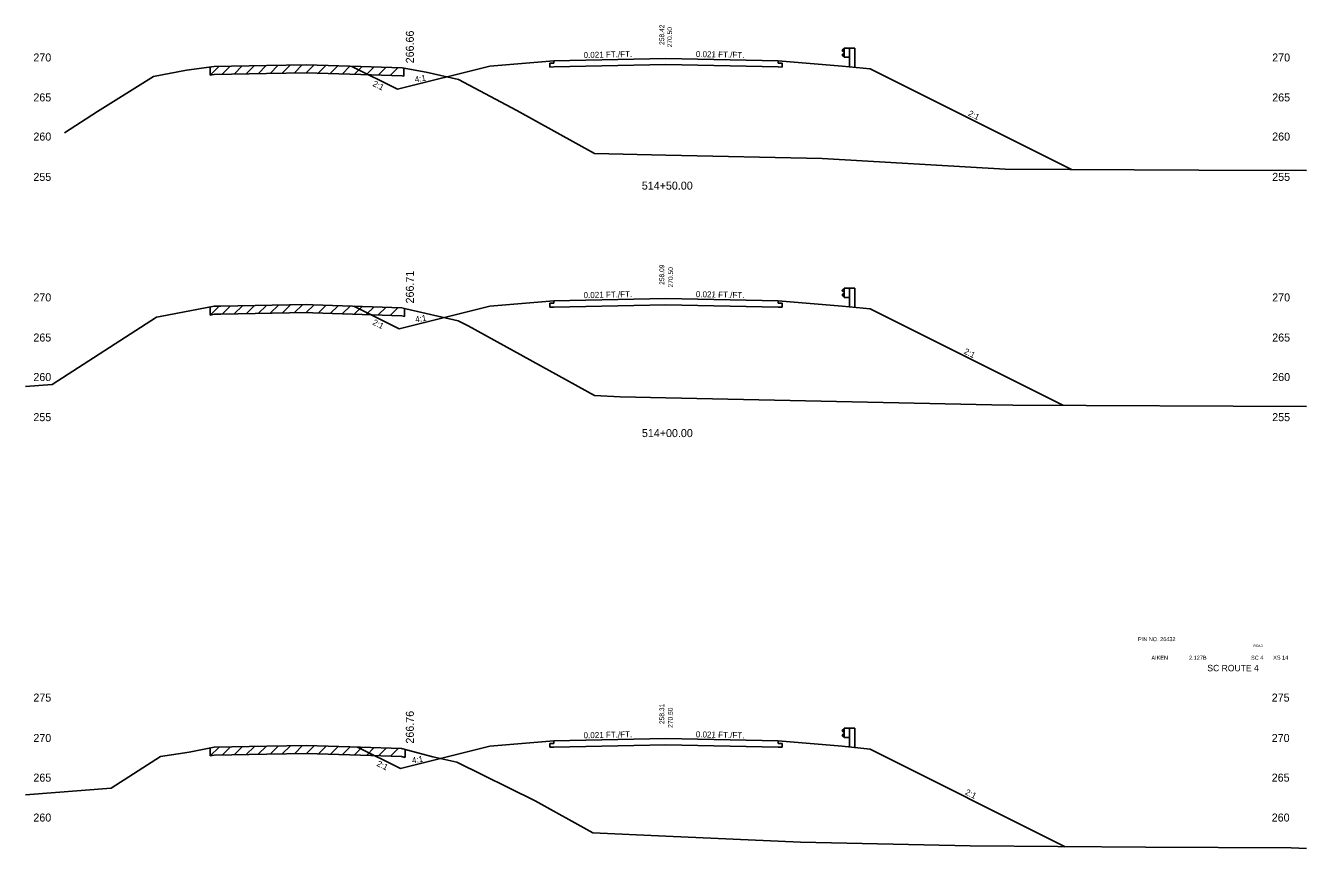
# Model space of a CAD drawing. Extents: x 883 to 1160, y 1002 to 4323.
# Drawn here: x 1000 to 1160, y 2571.8 to 2674.6 of the extents above; entities that cross this region are included whole.
import ezdxf

# ---------------------------------------------------------------- set-up
doc = ezdxf.new("R2010")
doc.units = 0
for name, color, linetype in [('Level 1', 7, 'Continuous'), ('Level 10', 7, 'Continuous'), ('Level 11', 7, 'Continuous'), ('Level 12', 7, 'Continuous'), ('Level 24', 7, 'Continuous'), ('Level 3', 7, 'Continuous'), ('Level 32', 7, 'Continuous'), ('Level 33', 7, 'Continuous'), ('Level 59', 7, 'Continuous'), ('Level 6', 7, 'Continuous'), ('Level 60', 7, 'Continuous'), ('Level 61', 7, 'Continuous'), ('Level 7', 7, 'Continuous')]:
    doc.layers.add(name, color=color, linetype=linetype)

msp = doc.modelspace()

# ---------------------------------------------------------------- linework, layer by layer
at = {"layer": 'Level 11'}
for p, q in [((1066, 2669.91), (1065.5, 2669.9)), ((1065.5, 2669.9), (1065.5, 2669.42)), ((1065.5, 2669.42), (1066, 2669.43)), ((1066, 2670.21), (1066, 2669.91)), ((1094, 2669.91), (1094, 2670.21)), ((1094.5, 2669.9), (1094, 2669.91)), ((1094, 2669.43), (1094.5, 2669.42)), ((1094.5, 2669.42), (1094.5, 2669.9)), ((1066, 2640.21), (1066, 2639.91)), ((1094, 2639.91), (1094, 2640.21)), ((1066, 2639.91), (1065.5, 2639.9)), ((1065.5, 2639.9), (1065.5, 2639.42)), ((1065.5, 2639.42), (1066, 2639.43)), ((1094.5, 2639.9), (1094, 2639.91)), ((1094, 2639.43), (1094.5, 2639.42)), ((1094.5, 2639.42), (1094.5, 2639.9)), ((1066, 2584.91), (1065.5, 2584.9)), ((1065.5, 2584.9), (1065.5, 2584.42)), ((1065.5, 2584.42), (1066, 2584.43)), ((1066, 2585.21), (1066, 2584.91)), ((1094, 2584.91), (1094, 2585.21)), ((1094.5, 2584.9), (1094, 2584.91)), ((1094, 2584.43), (1094.5, 2584.42)), ((1094.5, 2584.42), (1094.5, 2584.9))]:
    msp.add_line(p, q, dxfattribs=at)
at = {"layer": 'Level 12'}
for p, q in [((1080, 2669.72), (1066, 2669.43)), ((1094, 2669.43), (1080, 2669.72)), ((1080, 2639.72), (1066, 2639.43)), ((1094, 2639.43), (1080, 2639.72)), ((1080, 2584.72), (1066, 2584.43)), ((1094, 2584.43), (1080, 2584.72))]:
    msp.add_line(p, q, dxfattribs=at)
at = {"layer": 'Level 24'}
for p, q in [((1102.27, 2671.72), (1102, 2671.52)), ((1102, 2671.52), (1102, 2671.47)), ((1102, 2671.47), (1102.27, 2671.27)), ((1102, 2670.95), (1102.27, 2671.15)), ((1102, 2670.9), (1102, 2670.95)), ((1102.27, 2670.7), (1102, 2670.9)), ((1102.27, 2670.63), (1102.27, 2671.79)), ((1102.27, 2671.79), (1102.94, 2671.79)), ((1102.27, 2670.63), (1102.94, 2670.63)), ((1102.94, 2671.79), (1102.94, 2669.45)), ((1102.94, 2671.79), (1103.6, 2671.79)), ((1103.6, 2671.79), (1103.6, 2669.38)), ((1102.27, 2641.72), (1102, 2641.52)), ((1102.27, 2640.63), (1102.27, 2641.79)), ((1102.27, 2641.79), (1102.94, 2641.79)), ((1102.94, 2641.79), (1102.94, 2639.45)), ((1102.94, 2641.79), (1103.6, 2641.79)), ((1103.6, 2641.79), (1103.6, 2639.38)), ((1102, 2641.52), (1102, 2641.47)), ((1102, 2641.47), (1102.27, 2641.27)), ((1102, 2640.95), (1102.27, 2641.15)), ((1102, 2640.9), (1102, 2640.95)), ((1102.27, 2640.7), (1102, 2640.9)), ((1102.27, 2640.63), (1102.94, 2640.63)), ((1102.27, 2586.72), (1102, 2586.52)), ((1102, 2586.52), (1102, 2586.47)), ((1102, 2586.47), (1102.27, 2586.27)), ((1102, 2585.95), (1102.27, 2586.15)), ((1102, 2585.9), (1102, 2585.95)), ((1102.27, 2585.7), (1102, 2585.9)), ((1102.27, 2585.63), (1102.27, 2586.79)), ((1102.27, 2586.79), (1102.94, 2586.79)), ((1102.27, 2585.63), (1102.94, 2585.63)), ((1102.94, 2586.79), (1102.94, 2584.45)), ((1102.94, 2586.79), (1103.6, 2586.79)), ((1103.6, 2586.79), (1103.6, 2584.38))]:
    msp.add_line(p, q, dxfattribs=at)
at = {"layer": 'Level 59'}
for p, q in [((1066, 2670.21), (1080, 2670.5)), ((1080, 2670.5), (1094, 2670.21)), ((1066, 2640.21), (1080, 2640.5)), ((1080, 2640.5), (1094, 2640.21)), ((1066, 2585.21), (1080, 2585.5)), ((1080, 2585.5), (1094, 2585.21))]:
    msp.add_line(p, q, dxfattribs=at)
at = {"layer": 'Level 6'}
for p, q in [((1058, 2669.54), (1066, 2670.21)), ((1094, 2670.21), (1102, 2669.54)), ((1102, 2669.54), (1105.5, 2669.19)), ((1058, 2639.54), (1066, 2640.21)), ((1094, 2640.21), (1102, 2639.54)), ((1102, 2639.54), (1105.5, 2639.19)), ((1058, 2584.54), (1066, 2585.21)), ((1094, 2585.21), (1102, 2584.54)), ((1102, 2584.54), (1105.5, 2584.19))]:
    msp.add_line(p, q, dxfattribs=at)
at = {"layer": 'Level 60'}
for p, q in [((1015.97, 2668.23), (1020.09, 2669.02)), ((1020.09, 2669.02), (1023.54, 2669.49)), ((1023.54, 2669.49), (1030.09, 2669.6)), ((1030.09, 2669.6), (1035.05, 2669.69)), ((1035.05, 2669.69), (1041.88, 2669.47)), ((1041.88, 2669.47), (1047.05, 2669.31)), ((1047.05, 2669.31), (1050.04, 2668.79)), ((1008.99, 2663.87), (1015.97, 2668.23)), ((1050.04, 2668.79), (1054.08, 2667.85)), ((1054.08, 2667.85), (1061.38, 2663.98)), ((1004.85, 2661.21), (1008.99, 2663.87)), ((1061.38, 2663.98), (1071.07, 2658.62)), ((1071.07, 2658.62), (1080, 2658.42)), ((1080, 2658.42), (1099.5, 2658)), ((1099.5, 2658), (1122.38, 2656.65)), ((1122.38, 2656.65), (1146.55, 2656.54)), ((1146.55, 2656.54), (1160, 2656.5)), ((1016.8, 2638.23), (1023.55, 2639.53)), ((1023.55, 2639.53), (1024.37, 2639.54)), ((1024.37, 2639.54), (1035.07, 2639.73)), ((1035.07, 2639.73), (1035.89, 2639.7)), ((1035.89, 2639.7), (1047.01, 2639.34)), ((1047.01, 2639.34), (1047.5, 2639.21)), ((1047.5, 2639.21), (1054.05, 2637.69)), ((1003.31, 2629.77), (1016.36, 2638.16)), ((1016.36, 2638.16), (1016.8, 2638.23)), ((1054.05, 2637.69), (1055.28, 2637.08)), ((1055.28, 2637.08), (1071.05, 2628.36)), ((1000, 2629.52), (1003.31, 2629.77)), ((1071.05, 2628.36), (1074.27, 2628.22)), ((1074.27, 2628.22), (1080, 2628.09)), ((1080, 2628.09), (1120.7, 2627.2)), ((1120.7, 2627.2), (1123.34, 2627.18)), ((1123.34, 2627.18), (1160, 2627.01)), ((1020.44, 2583.83), (1023.56, 2584.43)), ((1023.56, 2584.43), (1030.15, 2584.56)), ((1030.15, 2584.56), (1035.09, 2584.65)), ((1035.09, 2584.65), (1041.83, 2584.44)), ((1041.83, 2584.44), (1046.96, 2584.27)), ((1046.96, 2584.27), (1050.87, 2583.24)), ((1010.7, 2579.31), (1016.84, 2583.25)), ((1016.84, 2583.25), (1020.44, 2583.83)), ((1050.87, 2583.24), (1053.88, 2582.54)), ((1053.88, 2582.54), (1063.64, 2577.72)), ((1000, 2578.48), (1010.7, 2579.31)), ((1063.64, 2577.72), (1070.88, 2573.71)), ((1070.88, 2573.71), (1080, 2573.31)), ((1080, 2573.31), (1096.8, 2572.56)), ((1096.8, 2572.56), (1118, 2572.1)), ((1118, 2572.1), (1139.92, 2571.92)), ((1139.92, 2571.92), (1158.11, 2571.84)), ((1158.11, 2571.84), (1160, 2571.79))]:
    msp.add_line(p, q, dxfattribs=at)
at = {"layer": 'Level 61'}
for p, q in [((1024.12, 2669.5), (1023.05, 2668.42)), ((1023.05, 2669.42), (1023.05, 2668.42)), ((1025.56, 2669.52), (1024.55, 2668.51)), ((1027.06, 2669.55), (1026.05, 2668.53)), ((1028.56, 2669.58), (1027.55, 2668.56)), ((1030.06, 2669.6), (1029.05, 2668.58)), ((1031.56, 2669.63), (1030.55, 2668.61)), ((1033.06, 2669.65), (1032.05, 2668.64)), ((1034.56, 2669.68), (1033.55, 2668.66)), ((1036.01, 2669.66), (1035.05, 2668.69)), ((1037.51, 2669.61), (1036.55, 2668.64)), ((1039.01, 2669.56), (1038.05, 2668.59)), ((1040.51, 2669.51), (1039.55, 2668.54)), ((1042.01, 2669.46), (1041.05, 2668.49)), ((1043.52, 2669.42), (1042.55, 2668.45)), ((1045.02, 2669.37), (1044.05, 2668.4)), ((1046.52, 2669.32), (1045.55, 2668.35)), ((1047.25, 2668.27), (1047.25, 2669.27)), ((1023.05, 2668.42), (1023.54, 2668.49)), ((1023.54, 2668.49), (1030.09, 2668.6)), ((1030.09, 2668.6), (1035.05, 2668.69)), ((1035.05, 2668.69), (1041.88, 2668.47)), ((1041.88, 2668.47), (1047.05, 2668.31)), ((1047.05, 2668.31), (1047.25, 2668.27)), ((1024.16, 2639.54), (1023.06, 2638.43)), ((1023.06, 2639.43), (1023.06, 2638.43)), ((1023.06, 2638.43), (1023.55, 2638.53)), ((1023.55, 2638.53), (1024.37, 2638.54)), ((1024.37, 2638.54), (1035.07, 2638.73)), ((1025.58, 2639.56), (1024.56, 2638.55)), ((1027.08, 2639.59), (1026.06, 2638.57)), ((1028.58, 2639.62), (1027.56, 2638.6)), ((1030.08, 2639.64), (1029.06, 2638.62)), ((1031.58, 2639.67), (1030.56, 2638.65)), ((1033.08, 2639.69), (1032.06, 2638.68)), ((1034.58, 2639.72), (1033.56, 2638.7)), ((1036.03, 2639.7), (1035.06, 2638.73)), ((1035.07, 2638.73), (1035.89, 2638.7)), ((1035.89, 2638.7), (1047.01, 2638.34)), ((1037.53, 2639.65), (1036.56, 2638.68)), ((1039.03, 2639.6), (1038.06, 2638.63)), ((1040.53, 2639.55), (1039.56, 2638.58)), ((1042.03, 2639.5), (1041.06, 2638.53)), ((1043.53, 2639.45), (1042.56, 2638.49)), ((1045.03, 2639.4), (1044.06, 2638.44)), ((1046.53, 2639.36), (1045.56, 2638.39)), ((1047.33, 2638.26), (1047.33, 2639.26)), ((1047.01, 2638.34), (1047.33, 2638.26)), ((1024.18, 2584.44), (1023.07, 2583.34)), ((1023.07, 2584.34), (1023.07, 2583.34)), ((1025.59, 2584.47), (1024.57, 2583.45)), ((1027.09, 2584.5), (1026.07, 2583.48)), ((1028.59, 2584.53), (1027.57, 2583.51)), ((1030.09, 2584.56), (1029.07, 2583.54)), ((1031.59, 2584.59), (1030.57, 2583.57)), ((1033.09, 2584.61), (1032.07, 2583.6)), ((1034.59, 2584.64), (1033.57, 2583.62)), ((1036.04, 2584.62), (1035.07, 2583.65)), ((1037.54, 2584.57), (1036.57, 2583.6)), ((1039.04, 2584.52), (1038.07, 2583.56)), ((1040.54, 2584.48), (1039.57, 2583.51)), ((1042.04, 2584.43), (1041.07, 2583.46)), ((1043.54, 2584.38), (1042.57, 2583.41)), ((1045.04, 2584.33), (1044.07, 2583.36)), ((1046.54, 2584.28), (1045.57, 2583.32)), ((1047.41, 2583.15), (1047.41, 2584.15)), ((1023.07, 2583.34), (1023.56, 2583.43)), ((1023.56, 2583.43), (1030.15, 2583.56)), ((1030.15, 2583.56), (1035.09, 2583.65)), ((1035.09, 2583.65), (1041.83, 2583.44)), ((1041.83, 2583.44), (1046.96, 2583.27)), ((1046.96, 2583.27), (1047.41, 2583.15))]:
    msp.add_line(p, q, dxfattribs=at)
at = {"layer": 'Level 7'}
for p, q in [((1040.76, 2669.5), (1046.45, 2666.66)), ((1058, 2669.54), (1046.45, 2666.66)), ((1105.5, 2669.19), (1130.66, 2656.61)), ((1040.99, 2639.54), (1046.65, 2636.71)), ((1058, 2639.54), (1046.65, 2636.71)), ((1105.5, 2639.19), (1129.59, 2627.15)), ((1041.47, 2584.45), (1046.85, 2581.76)), ((1058, 2584.54), (1046.85, 2581.76)), ((1105.5, 2584.19), (1129.88, 2572))]:
    msp.add_line(p, q, dxfattribs=at)

# ---------------------------------------------------------------- texts
at = {"layer": 'Level 1'}
for s, height, p in [('514+50.00', 1, (1076.98, 2654.1)), ('514+00.00', 1, (1076.99, 2623.18)), ('PIN NO. 26432', 0.5, (1138.97, 2597.68)), ('AIKEN', 0.5, (1140.64, 2595.36)), (' 2.127B', 0.5, (1145.15, 2595.36)), ('SC 4', 0.5, (1153.09, 2595.36)), ('XS 14', 0.5, (1155.85, 2595.38)), ('SC ROUTE 4', 0.8, (1147.63, 2593.92))]:
    msp.add_text(s, height=height, dxfattribs=at).set_placement(p)
at = {"layer": 'Level 10'}
for s, p in [('258.42', (1079.78, 2672.18)), ('258.09', (1079.78, 2642.2)), ('258.31', (1079.78, 2587.32))]:
    msp.add_text(s, height=0.6, rotation=90, dxfattribs=at).set_placement(p)
at = {"layer": 'Level 3'}
for s, height, p in [(' 270', 1, (1000.6, 2670.11)), (' 270', 1, (1155.36, 2670.11)), (' 265', 1, (1000.6, 2665.12)), (' 265', 1, (1155.36, 2665.12)), (' 260', 1, (1000.6, 2660.23)), (' 260', 1, (1155.36, 2660.23)), (' 255', 1, (1000.6, 2655.19)), (' 255', 1, (1155.36, 2655.19)), (' 270', 1, (1000.6, 2640.13)), (' 270', 1, (1155.36, 2640.13)), (' 265', 1, (1000.6, 2635.12)), (' 265', 1, (1155.36, 2635.12)), (' 260', 1, (1000.6, 2630.18)), (' 260', 1, (1155.36, 2630.18)), (' 255', 1, (1000.6, 2625.17)), (' 255', 1, (1155.36, 2625.17)), ('ROAD', 0.3, (1153.38, 2596.95)), (' 275', 1, (1000.6, 2590.13)), (' 275', 1, (1155.3, 2590.13)), (' 270', 1, (1000.6, 2585.08)), (' 270', 1, (1155.3, 2585.08)), (' 265', 1, (1000.6, 2580.13)), (' 265', 1, (1155.3, 2580.13)), (' 260', 1, (1000.6, 2575.14)), (' 260', 1, (1155.3, 2575.14))]:
    msp.add_text(s, height=height, dxfattribs=at).set_placement(p)
at = {"layer": 'Level 32'}
for s, rotation, p in [('0.021 FT./FT.', 1.1916, (1069.71, 2670.54)), ('0.021 FT./FT.', 358.8084, (1083.72, 2670.67)), ('2:1', 333.435, (1043.28, 2667.09)), ('4:1', 9.4623, (1048.68, 2667.5)), ('2:1', 333.435, (1117.68, 2663.38)), ('0.021 FT./FT.', 1.1916, (1069.71, 2640.54)), ('0.021 FT./FT.', 358.8084, (1083.72, 2640.67)), ('4:1', 9.4623, (1048.74, 2637.5)), ('2:1', 333.435, (1043.27, 2637.27)), ('2:1', 333.435, (1117.15, 2633.65)), ('0.021 FT./FT.', 1.1916, (1069.71, 2585.54)), ('0.021 FT./FT.', 358.8084, (1083.72, 2585.67)), ('2:1', 333.435, (1043.79, 2582.14)), ('4:1', 9.4623, (1048.33, 2582.4)), ('2:1', 333.435, (1117.3, 2578.57))]:
    msp.add_text(s, height=0.75, rotation=rotation, dxfattribs=at).set_placement(p)
at = {"layer": 'Level 33'}
for s, p in [('266.66', (1048.5, 2669.88)), ('266.71', (1048.5, 2639.88)), ('266.76', (1048.5, 2584.88))]:
    msp.add_text(s, height=1, rotation=90, dxfattribs=at).set_placement(p)
at = {"layer": 'Level 59'}
for p in [(1080.76, 2671.65), (1080.88, 2641.65), (1080.85, 2586.62)]:
    msp.add_text(' 270.50', height=0.6, rotation=90, dxfattribs=at).set_placement(p)

doc.saveas('drawing.dxf')
